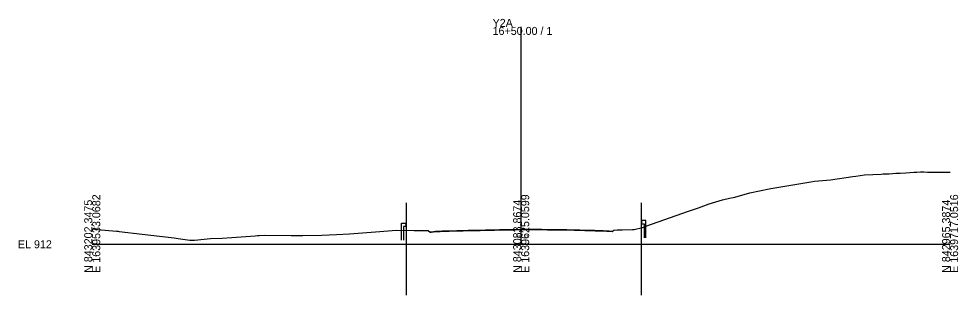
# Model space of a CAD drawing. Extents: x -26 to 303, y -10 to 10517.
# Drawn here: x -25.7 to 302.8, y 5982.2 to 6078.9 of the extents above; entities that cross this region are included whole.
import ezdxf

# ---------------------------------------------------------------- set-up
doc = ezdxf.new("R2010")
doc.units = 0
for name, color, linetype in [('Exist Cross Section Cell', 7, 'Continuous'), ('Exist XS Center Line Elevation Label', 7, 'Continuous'), ('Exist XS Ground Line', 7, 'Continuous'), ('Prop CMT Guardrail Widen Shoulder', 7, 'Continuous'), ('Prop CMT Pvmt Surface Overlay', 7, 'Continuous'), ('Scratch_Level_0', 7, 'Continuous')]:
    doc.layers.add(name, color=color, linetype=linetype)

msp = doc.modelspace()

# ---------------------------------------------------------------- linework, layer by layer
at = {"layer": 'Exist Cross Section Cell'}
for p, q in [((150, 6000), (150, 6076.06)), ((0, 6000), (150, 6000)), ((150, 6000), (300, 6000))]:
    msp.add_line(p, q, dxfattribs=at)
at = {"layer": 'Exist XS Ground Line'}
msp.add_lwpolyline([(0, 6005.38), (1.88, 6005.19), (8.45, 6004.61), (9.01, 6004.54), (9.44, 6004.5), (17.5, 6003.52), (23.54, 6002.81), (28.6, 6002.23), (30.04, 6002.07), (34.1, 6001.49), (35.73, 6001.41), (41.37, 6002), (45.44, 6002.1), (48.78, 6002.42), (56.94, 6002.98), (57.8, 6003.04), (58.35, 6003.06), (60.09, 6003.16), (69.53, 6003.06), (72.75, 6003.03), (73.68, 6003.02), (80.28, 6003.16), (85.41, 6003.43), (89.98, 6003.7), (94.54, 6004.02), (99.07, 6004.4), (106.42, 6004.96), (112.62, 6004.87), (116.73, 6004.79), (117.47, 6004.78), (118.12, 6004.24), (118.56, 6004.29), (120.1, 6004.43), (120.47, 6004.45), (121.66, 6004.51), (122.42, 6004.54), (123.41, 6004.58), (124.21, 6004.62), (124.83, 6004.64), (127.48, 6004.68), (127.99, 6004.7), (129.77, 6004.75), (131.51, 6004.81), (132.36, 6004.81), (134.32, 6004.84), (135.63, 6004.86), (137.49, 6004.9), (138.46, 6004.91), (139.71, 6004.95), (140.65, 6004.98), (142.42, 6005.01), (143.84, 6005.04), (146.16, 6005.09), (146.95, 6005.09), (147.86, 6005.11), (150.15, 6005.13), (150.93, 6005.13), (151.94, 6005.14), (152.71, 6005.15), (153.31, 6005.15), (156.02, 6005.13), (156.43, 6005.13), (157.27, 6005.12), (159.25, 6005.1), (160.09, 6005.09), (161.62, 6005.07), (162.81, 6005.07), (164.17, 6005.05), (165.97, 6005.02), (168.48, 6004.99), (169.14, 6004.98), (170.53, 6004.93), (172.32, 6004.86), (175.47, 6004.77), (175.88, 6004.76), (176.4, 6004.74), (177.66, 6004.7), (178.63, 6004.68), (179.91, 6004.63), (180.77, 6004.58), (181.84, 6004.51), (182.46, 6004.99), (183.54, 6005.04), (184.44, 6005.08), (185.32, 6005.11), (188.95, 6005.2), (189.51, 6005.21), (192.41, 6005.91), (192.83, 6006.01), (193.63, 6006.32), (208.57, 6011.61), (212.02, 6012.77), (215.7, 6014.21), (220.44, 6015.52), (222.83, 6016.13), (224.68, 6016.53), (229.96, 6017.98), (236.75, 6019.43), (237.34, 6019.55), (239.42, 6019.9), (251.33, 6021.89), (252.54, 6022.04), (258.14, 6022.59), (265.94, 6023.69), (267.05, 6023.84), (270.06, 6024.27), (275.86, 6024.55), (276.57, 6024.6), (277.47, 6024.65), (278.64, 6024.71), (281.02, 6024.83), (282.56, 6024.94), (284.56, 6025.03), (287.3, 6025.22), (288.35, 6025.28), (289.68, 6025.35), (290.41, 6025.34), (290.84, 6025.32), (292.11, 6025.29), (292.58, 6025.26), (294.62, 6025.25), (295.22, 6025.24), (295.74, 6025.24), (298.91, 6025.24), (299.65, 6025.25), (300, 6025.25)], dxfattribs=at)
at = {"layer": 'Prop CMT Guardrail Widen Shoulder'}
for points in [[(108.18, 6001.41), (108.18, 6007.41)], [(108.18, 6007.41), (109.51, 6007.41), (109.78, 6007.12)], [(109.78, 6006.53), (109.51, 6006.24), (108.84, 6006.24)], [(108.84, 6006.24), (108.84, 6001.41)], [(109.78, 6007.12), (109.51, 6006.83)], [(109.51, 6006.83), (109.78, 6006.53)], [(193.62, 6008.31), (192.29, 6008.31), (192.02, 6008.02)], [(192.02, 6008.02), (192.29, 6007.73)], [(192.29, 6007.73), (192.02, 6007.44)], [(192.02, 6007.44), (192.29, 6007.15), (192.96, 6007.15)], [(192.96, 6007.15), (192.96, 6002.31)], [(193.62, 6002.31), (193.62, 6008.31)]]:
    msp.add_lwpolyline(points, dxfattribs=at)
at = {"layer": 'Prop CMT Pvmt Surface Overlay'}
msp.add_lwpolyline([(117.98, 6004.36), (118.55, 6004.41), (120.09, 6004.55), (120.47, 6004.58), (121.66, 6004.64), (122.42, 6004.66), (123.4, 6004.71), (124.2, 6004.74), (124.82, 6004.76), (127.48, 6004.81), (127.99, 6004.82), (129.76, 6004.88), (131.51, 6004.93), (132.36, 6004.94), (134.32, 6004.96), (135.63, 6004.99), (137.49, 6005.02), (138.46, 6005.04), (139.71, 6005.07), (140.65, 6005.1), (142.42, 6005.14), (143.84, 6005.16), (146.16, 6005.21), (146.95, 6005.22), (147.86, 6005.23), (150.15, 6005.26), (150.93, 6005.26), (151.94, 6005.27), (152.71, 6005.27), (156.02, 6005.26), (156.43, 6005.26), (157.27, 6005.25), (159.25, 6005.23), (160.09, 6005.22), (161.62, 6005.2), (162.81, 6005.19), (164.17, 6005.17), (165.98, 6005.14), (168.49, 6005.11), (169.14, 6005.1), (170.54, 6005.05), (172.33, 6004.99), (175.47, 6004.9), (175.88, 6004.88), (176.4, 6004.87), (177.66, 6004.83), (178.64, 6004.81), (179.92, 6004.76), (180.78, 6004.71), (181.99, 6004.62)], dxfattribs=at)
at = {"layer": 'Scratch_Level_0'}
for p, q in [((109.78, 6014.51), (109.78, 5982.18)), ((192.02, 6014.51), (192.02, 5982.18)), ((109.78, 6007.12), (109.78, 6004.91)), ((192.02, 6008.02), (192.02, 6005.81))]:
    msp.add_line(p, q, dxfattribs=at)

# ---------------------------------------------------------------- texts
at = {"layer": 'Exist Cross Section Cell'}
for s, p in [('Y2A', (140, 6076.06)), ('16+50.00 / 1', (140, 6073.26)), ('EL 912', (-26, 5998.6))]:
    msp.add_text(s, height=2.8, dxfattribs=at).set_placement(p)
for s, p in [('N 843202.3475', (0, 5990)), ('E 1639533.0682', (2.8, 5990)), ('N 843083.8674', (150, 5990)), ('E 1639625.0599', (152.8, 5990)), ('N 842965.3874', (300, 5990)), ('E 1639717.0516', (302.8, 5990))]:
    msp.add_text(s, height=2.8, rotation=90, dxfattribs=at).set_placement(p)
at = {"layer": 'Exist XS Center Line Elevation Label'}
msp.add_text('917.13', height=1, dxfattribs=at).set_placement((148.27, 6002.27))

doc.saveas('drawing.dxf')
